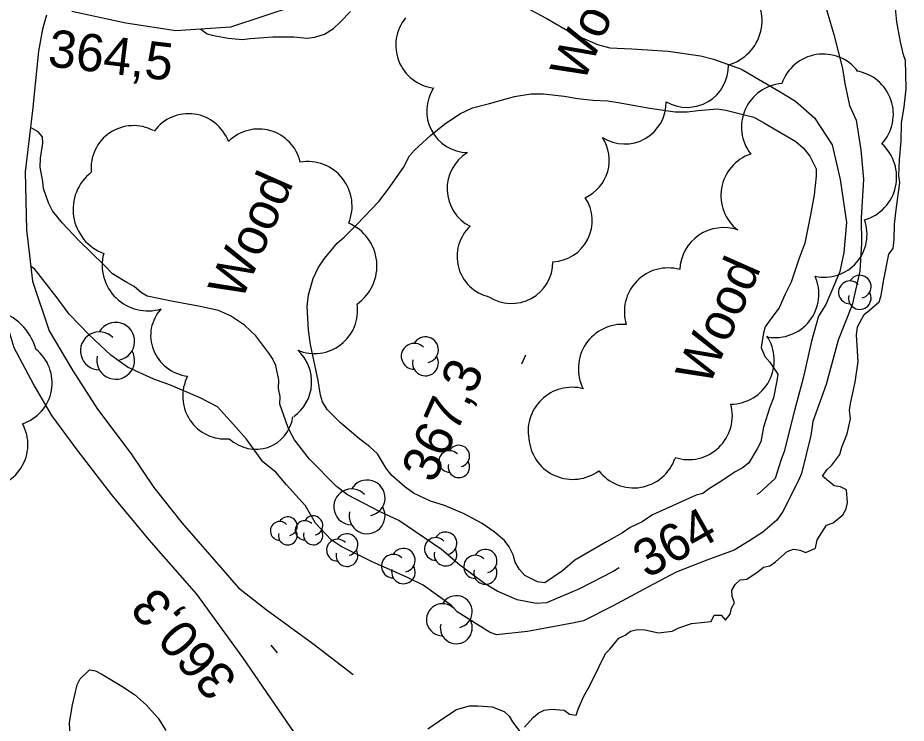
# Model space of a CAD drawing. Extents: x 287698 to 290158, y 5234163 to 5237182.
# Drawn here: x 289209.7 to 289281.1, y 5235213.3 to 5235270 of the extents above; entities that cross this region are included whole.
import ezdxf

# ---------------------------------------------------------------- set-up
doc = ezdxf.new("R2010")
doc.units = 0
for name, color, linetype in [('Niveau 19', 7, 'Continuous'), ('Niveau 2', 7, 'Continuous'), ('Niveau 3', 7, 'Continuous'), ('Niveau 4', 7, 'Continuous'), ('Niveau 44', 7, 'Continuous')]:
    doc.layers.add(name, color=color, linetype=linetype)

msp = doc.modelspace()

# ---------------------------------------------------------------- linework, layer by layer
at = {"layer": 'Niveau 19'}
for points in [[(289232.57, 5235211.58), (289227.76, 5235218.58), (289224.07, 5235223.68), (289220.24, 5235228.03), (289217.23, 5235231.65), (289214.46, 5235235.29), (289212.4, 5235238.04), (289210.9, 5235240.6), (289209.38, 5235243.49), (289208.5, 5235246.43), (289207.63, 5235250.16), (289207.48, 5235253.53), (289207.66, 5235257.1), (289208.2, 5235260.15), (289208.45, 5235264.13), (289208.52, 5235267.65), (289208.02, 5235270.78), (289206.62, 5235272.53), (289205, 5235274.04), (289203.18, 5235274.74), (289201.27, 5235274.81)], [(289231.96, 5235270.99), (289226.78, 5235269.26), (289222.39, 5235268.98), (289218.37, 5235269.59), (289214.03, 5235270.54)], [(289211.99, 5235270.23), (289211.65, 5235269.11), (289211.33, 5235267.33), (289210.86, 5235262.57), (289210.26, 5235257.65), (289210.39, 5235252.98), (289210.85, 5235248.84), (289212.2, 5235244.86), (289214.08, 5235241.69), (289216.09, 5235238.55), (289218.78, 5235234.95), (289220.62, 5235232.25), (289222.88, 5235229.39), (289225.43, 5235226.47), (289227.42, 5235224.17), (289229.63, 5235222.43), (289233.4, 5235219.7), (289236.64, 5235217.22)]]:
    msp.add_lwpolyline(points, dxfattribs=at)
at = {"layer": 'Niveau 2'}
for points in [[(289249.52, 5235271.4), (289252.15, 5235270.01), (289254.36, 5235268.71), (289256.28, 5235267.88), (289257.25, 5235267.62), (289259.02, 5235267.53), (289261.95, 5235267.35), (289264.54, 5235266.97), (289265.58, 5235266.71), (289267.83, 5235265.89), (289268.88, 5235265.27), (289270.96, 5235264.06), (289272.17, 5235263.31), (289273.72, 5235261.99), (289275.13, 5235259.81), (289275.78, 5235257.02), (289276.27, 5235253.55), (289276.06, 5235251.16), (289275.75, 5235249.63), (289275.1, 5235248.08), (289274.61, 5235246.97), (289274.03, 5235246.03), (289273.47, 5235244.03), (289272.79, 5235241.03), (289272.09, 5235238.45), (289271.27, 5235235.15), (289271.01, 5235234.43), (289270.54, 5235232.97), (289269.27, 5235231.79), (289269.08, 5235231.68)], [(289224.39, 5235269.11), (289224.91, 5235268.73), (289225.43, 5235268.59), (289226.58, 5235268.39), (289227.71, 5235268.27), (289228.34, 5235268.35), (289230.17, 5235268.49), (289231.87, 5235268.49), (289232.93, 5235268.39), (289233.56, 5235268.48), (289234.33, 5235268.71), (289235.04, 5235269.17), (289235.62, 5235269.7), (289236.41, 5235270.52)], [(289274.58, 5235270.97), (289275.27, 5235268.68), (289275.95, 5235265.94), (289276.14, 5235264.73), (289276.52, 5235262.97), (289277.05, 5235261.79), (289277.43, 5235259.42), (289277.65, 5235257.05), (289277.45, 5235253.91), (289277.49, 5235251.87), (289277.36, 5235249.66), (289276.73, 5235246.93), (289275.6, 5235244.11), (289274.65, 5235240.52), (289273.58, 5235237.57), (289273.41, 5235236.43), (289272.67, 5235233.37), (289272.41, 5235232.8), (289271.17, 5235230.33), (289270.67, 5235229.62), (289269.55, 5235228.66), (289268.43, 5235227.92), (289267.25, 5235227.22), (289265.06, 5235226.41), (289262.58, 5235225.43), (289260.32, 5235224.24), (289257.54, 5235222.74), (289255.13, 5235221.52), (289254.26, 5235221.33), (289250.63, 5235220.67), (289248.16, 5235220.41), (289247.59, 5235220.62), (289245, 5235222.25), (289244.53, 5235222.76), (289242.25, 5235224.4), (289241.04, 5235224.97), (289238.11, 5235226.29), (289235.67, 5235227.49), (289234.85, 5235228.04), (289233.61, 5235229.38), (289232.81, 5235230.78), (289231.28, 5235232.47)], [(289260.7, 5235230.05), (289259.87, 5235229.48), (289258.89, 5235229.02), (289258.29, 5235228.6), (289256.99, 5235227.88), (289254.45, 5235226.41), (289253.45, 5235225.54), (289252.04, 5235224.57), (289251.44, 5235224.65), (289250.44, 5235225.17), (289249.99, 5235225.64), (289249.65, 5235226.25), (289249.49, 5235226.84), (289249.18, 5235227.47), (289248.8, 5235227.98), (289247.97, 5235228.68), (289246.99, 5235229.36), (289245.55, 5235230.14), (289243.96, 5235230.8), (289242.84, 5235231.16), (289241.49, 5235231.79), (289240.79, 5235232.3), (289239.75, 5235233.21), (289239.3, 5235233.76), (289238.58, 5235234.96), (289237.98, 5235235.51), (289237.02, 5235236.25), (289235.6, 5235237.46), (289234.55, 5235238.51), (289234.17, 5235239.13), (289234, 5235239.67), (289233.81, 5235240.86), (289233.2, 5235243.75), (289233.04, 5235244.89), (289232.93, 5235246.8), (289233.05, 5235247.74), (289233.41, 5235249.05), (289233.82, 5235249.91), (289234.34, 5235250.68), (289235.35, 5235251.9), (289235.9, 5235252.39), (289236.94, 5235253.43), (289238.7, 5235255.25), (289239.47, 5235256.27), (289240.67, 5235257.99), (289241.16, 5235258.92), (289241.56, 5235259.37), (289242.85, 5235260.57), (289243.98, 5235261.47), (289245.21, 5235262.31), (289246.22, 5235262.78), (289247.58, 5235263.13), (289249.59, 5235263.69), (289250.91, 5235263.9), (289251.93, 5235263.9), (289253.6, 5235263.73), (289254.68, 5235263.54), (289255.9, 5235263.41), (289257.09, 5235263.36), (289257.94, 5235263.21), (289260.48, 5235262.76), (289262.52, 5235262.46), (289263.47, 5235262.46), (289264.37, 5235262.58), (289265.89, 5235262.7), (289266.58, 5235262.6), (289268.82, 5235262.04), (289269.69, 5235261.54), (289272.21, 5235260.08), (289272.82, 5235259.53), (289273.32, 5235258.91), (289273.83, 5235257.87), (289273.83, 5235257.28), (289273.67, 5235255.78), (289273.38, 5235254.19), (289272.92, 5235251.91), (289272.45, 5235250.62), (289271.84, 5235248.76), (289271.34, 5235247.79), (289270.88, 5235246.69), (289270.12, 5235245.71), (289269.75, 5235245.18), (289269.62, 5235244.68), (289269.43, 5235243.51), (289269.71, 5235242.79), (289270.12, 5235242.34), (289270.76, 5235241.37), (289270.68, 5235240.82), (289270.42, 5235239.46), (289270.13, 5235238.72), (289269.6, 5235237.11), (289269.39, 5235235.92), (289269.09, 5235235.35), (289268.42, 5235234.23), (289267.97, 5235233.86), (289267.34, 5235233.52), (289266.26, 5235232.78), (289265.19, 5235232.12), (289264.72, 5235231.77), (289264.19, 5235231.62), (289260.7, 5235230.05)], [(289231.39, 5235237.13), (289230.75, 5235238.96), (289230.77, 5235239.57), (289230.63, 5235240.22), (289230.66, 5235240.89), (289230.42, 5235242.05), (289230.16, 5235242.62), (289229.85, 5235243.06), (289228.81, 5235244.44), (289227.89, 5235245.31), (289226.76, 5235246.06), (289225.8, 5235246.49), (289224.34, 5235246.81), (289222.17, 5235247.2), (289220.07, 5235247.63), (289219.63, 5235247.91), (289219.03, 5235248.42), (289218.44, 5235248.73), (289217.3, 5235249.43), (289216.61, 5235250.13), (289214.59, 5235252.11), (289213.27, 5235253.5), (289212.47, 5235254.49), (289212.14, 5235255.14), (289211.73, 5235256.29), (289211.69, 5235256.86), (289211.47, 5235258.02), (289211.49, 5235258.75), (289211.7, 5235259.93), (289211.67, 5235260.44), (289211.31, 5235260.85), (289210.69, 5235261.2)], [(289231.28, 5235232.47), (289230.41, 5235233.47), (289229.37, 5235234.3), (289228.06, 5235236.14), (289227.02, 5235237.32), (289225.72, 5235238.73), (289224.34, 5235239.47), (289221.95, 5235240.49), (289220.61, 5235240.97), (289218.49, 5235241.94), (289217.16, 5235242.89), (289215.4, 5235244.54), (289213.81, 5235246.2), (289212.83, 5235247.5), (289211.01, 5235249.84), (289210.72, 5235250.03)], [(289258.01, 5235225.8), (289257.52, 5235225.5), (289254.83, 5235224.1), (289252.17, 5235222.98), (289251.34, 5235222.91), (289249.82, 5235223.21), (289248.21, 5235223.92), (289247.19, 5235224.53), (289245.19, 5235225.99), (289243.72, 5235227.26), (289240.29, 5235229.6), (289238.8, 5235230.28), (289236.17, 5235231.66), (289235.3, 5235232.34), (289233.13, 5235234.54), (289231.91, 5235236.07), (289231.53, 5235236.77), (289231.39, 5235237.13)]]:
    msp.add_lwpolyline(points, dxfattribs=at)
at = {"layer": 'Niveau 3'}
for p, q in [((289250.18, 5235242.19), (289250.5, 5235242.92)), ((289230.56, 5235218.96), (289230.04, 5235219.57))]:
    msp.add_line(p, q, dxfattribs=at)
at = {"layer": 'Niveau 4'}
for points in [[(289280.11, 5235252.16), (289280.13, 5235253.44), (289280.26, 5235254.59), (289280.56, 5235256.79), (289280.49, 5235257.31), (289280.54, 5235258.61), (289280.66, 5235260.11), (289280.71, 5235261.56), (289280.92, 5235262.86), (289281.08, 5235264.32), (289281.04, 5235265.48), (289281.03, 5235266.58), (289280.87, 5235267.06), (289280.63, 5235268.09), (289280.32, 5235269.71), (289280.23, 5235270.78)], [(289250.41, 5235212.96), (289251.1, 5235213.74), (289251.51, 5235214.11), (289251.99, 5235214.33), (289252.56, 5235214.41), (289253.58, 5235214.35), (289254.03, 5235214.01), (289254.55, 5235213.94), (289254.71, 5235214.42), (289255.15, 5235215.42), (289255.66, 5235216.32), (289256.39, 5235217.84), (289256.9, 5235218.89), (289257.27, 5235219.25), (289257.99, 5235220.14), (289258.48, 5235220.37), (289258.92, 5235220.68), (289259.46, 5235220.83), (289260.08, 5235220.8), (289261.17, 5235220.55), (289262.26, 5235220.7), (289262.81, 5235220.95), (289263.81, 5235221.3), (289264.86, 5235221.42), (289265.4, 5235221.47), (289265.65, 5235221.97), (289266.2, 5235221.98), (289266.56, 5235221.59), (289266.94, 5235222.05), (289267.05, 5235222.54), (289267.29, 5235222.98), (289267.09, 5235223.49), (289267.06, 5235224), (289267.34, 5235224.44), (289267.73, 5235224.82), (289268.27, 5235224.88), (289269.19, 5235225.49), (289269.62, 5235225.84), (289270.11, 5235225.94), (289270.57, 5235226.27), (289271.51, 5235227.09), (289272.01, 5235227.29), (289272.52, 5235227.2), (289273.02, 5235227.01), (289273.79, 5235227.38), (289273.93, 5235228.05), (289274.66, 5235229.22), (289275.21, 5235229.41), (289275.99, 5235230.06), (289276.26, 5235230.54), (289276.35, 5235231.05), (289276.28, 5235232.06), (289275.8, 5235232.31), (289275.3, 5235232.38), (289274.34, 5235233.15), (289274.7, 5235233.66), (289275.11, 5235234.05), (289275.75, 5235234.9), (289275.91, 5235235.5), (289276.34, 5235236.56), (289276.6, 5235237.77), (289276.52, 5235238.48), (289276.59, 5235239.01), (289276.98, 5235240.71), (289277.21, 5235242.38), (289277.08, 5235244.51), (289277.17, 5235245.17), (289277.71, 5235246.17), (289278.14, 5235246.5), (289278.91, 5235247.19), (289279.06, 5235247.7), (289279.26, 5235248.84), (289279.69, 5235251.02), (289280.03, 5235251.47), (289280.11, 5235252.16)], [(289213.96, 5235210.29), (289213.84, 5235213.36), (289214.08, 5235214.76), (289214.45, 5235216.38), (289214.69, 5235216.85), (289215.43, 5235217.59), (289215.93, 5235217.5), (289216.43, 5235217.23), (289218.03, 5235216.28), (289219.06, 5235215.59), (289219.99, 5235214.77), (289220.96, 5235213.69), (289221.58, 5235212.71)], [(289242.63, 5235212.83), (289244, 5235213.77), (289244.94, 5235214.4), (289245.99, 5235214.7), (289246.66, 5235214.7), (289247.8, 5235214.6), (289248.77, 5235214.23), (289249.17, 5235213.87), (289249.43, 5235213.4), (289250.03, 5235212.62)]]:
    msp.add_lwpolyline(points, dxfattribs=at)
at = {"layer": 'Niveau 44'}
for centre, radius, start, end in [((289265.799, 5235269.81), 3.695, 285.5604, 47.18561), ((289243.528, 5235267.827), 3.475, 140.66524, 262.76263), ((289263.462, 5235266.154), 3.33, 239.67009, 1.65005), ((289245.894, 5235262.536), 3.357, 146.66681, 268.55924), ((289258.453, 5235263.206), 3.328, 237.79671, 1.28085), ((289253.891, 5235258.577), 3.327, 294.74638, 33.02894), ((289276.715, 5235257.218), 3.595, 286.39801, 48.00964), ((289247.568, 5235256.281), 3.39, 121.23589, 243.02062), ((289252.516, 5235253.712), 3.326, 272.83475, 33.66784), ((289248.31, 5235250.83), 3.332, 133.16804, 256.46825), ((289249.351, 5235250.377), 3.329, 236.8458, 0.21911), ((289277.345, 5235248.401), 0.914, 282.26917, 149.72626), ((289276.559, 5235247.944), 0.914, 44.11537, 269.80396), ((289277.345, 5235247.487), 0.914, 166.93686, 29.62123), ((289217.545, 5235244.003), 1.524, 282.26917, 149.72626), ((289216.234, 5235243.24), 1.524, 44.11537, 269.80396), ((289242.438, 5235243.32), 1.044, 282.26917, 149.72626), ((289217.545, 5235242.478), 1.524, 166.93686, 29.62123), ((289241.54, 5235242.798), 1.044, 44.11537, 269.80396), ((289242.438, 5235242.276), 1.044, 166.93686, 29.62123), ((289245.126, 5235234.777), 0.867, 282.26917, 149.72626), ((289244.38, 5235234.343), 0.867, 44.11537, 269.80396), ((289245.126, 5235233.909), 0.867, 166.93686, 29.62123), ((289237.751, 5235231.409), 1.441, 282.26917, 149.72626), ((289236.512, 5235230.688), 1.441, 44.11537, 269.80396), ((289237.751, 5235229.968), 1.441, 166.93686, 29.62123), ((289231.379, 5235229.137), 0.754, 282.26917, 149.72626), ((289233.417, 5235229.187), 0.774, 282.26917, 149.72626), ((289230.731, 5235228.76), 0.754, 44.11537, 269.80396), ((289232.752, 5235228.801), 0.774, 44.11537, 269.80396), ((289231.379, 5235228.383), 0.754, 166.93686, 29.62123), ((289233.417, 5235228.414), 0.774, 166.93686, 29.62123), ((289236.13, 5235227.652), 0.877, 282.26917, 149.72626), ((289244.053, 5235227.759), 0.911, 282.26917, 149.72626), ((289235.375, 5235227.213), 0.877, 44.11537, 269.80396), ((289243.27, 5235227.304), 0.911, 44.11537, 269.80396), ((289236.13, 5235226.775), 0.877, 166.93686, 29.62123), ((289239.854, 5235225.925), 0.947, 44.11537, 269.80396), ((289240.668, 5235226.399), 0.947, 282.26917, 149.72626), ((289244.053, 5235226.849), 0.911, 166.93686, 29.62123), ((289247.253, 5235226.332), 0.934, 282.26917, 149.72626), ((289246.45, 5235225.865), 0.934, 44.11537, 269.80396), ((289240.668, 5235225.451), 0.947, 166.93686, 29.62123), ((289247.253, 5235225.398), 0.934, 166.93686, 29.62123), ((289244.918, 5235222.258), 1.288, 282.26917, 149.72626), ((289243.811, 5235221.614), 1.288, 44.11537, 269.80396), ((289244.918, 5235220.97), 1.288, 166.93686, 29.62123)]:
    msp.add_arc(centre, radius, start, end, dxfattribs=at)
for centre, major_axis, ratio, start_param, end_param in [((289274.405, 5235263.589), (-3.473, -0.565), 0.999941, 3.636133, 5.788645), ((289276.534, 5235262.271), (-1.154, 3.321), 0.999942, 3.633828, 5.790949), ((289271.36, 5235261.23), (-1.42, -3.222), 0.999941, 3.636476, 5.788302), ((289223.416, 5235258.889), (-1.956, 2.823), 0.99207, 4.465254, 6.61704), ((289218.983, 5235257.923), (-0.604, 3.378), 0.996398, 5.616192, 7.772057), ((289229.034, 5235257.647), (1.206, 3.217), 0.999385, 5.297747, 7.425495), ((289269.703, 5235255.735), (-0.59, -3.469), 0.999942, 3.635158, 5.78962), ((289232.962, 5235254.885), (3.254, 1.5), 0.999934, 5.457202, 7.585172), ((289217.896, 5235254.619), (-3.735, -0.584), 0.998166, 5.217088, 7.343676), ((289234.796, 5235250.069), (3.724, 0.379), 0.999995, 5.220783, 7.347746), ((289266.398, 5235249.63), (-2.584, -2.391), 0.999942, 3.635528, 5.492917), ((289274.486, 5235252.608), (2.596, -2.266), 0.999978, 5.217526, 7.344628), ((289220.142, 5235250.139), (-2.562, -2.65), 0.999516, 5.222561, 7.343043), ((289261.947, 5235246.389), (-2.473, -2.507), 0.999941, 3.651655, 5.787423), ((289270.55, 5235247.818), (2.158, 2.769), 0.999942, 3.633217, 5.791561), ((289206.926, 5235242.231), (1.04, 4.23), 0.999831, 5.218071, 7.34518), ((289233.522, 5235246.476), (2.129, -2.725), 0.999731, 5.221059, 7.342888), ((289223.779, 5235244.421), (3.39, -0.523), 0.951355, 2.56843, 4.723971), ((289258.29, 5235241.811), (-2.961, 1.977), 0.999995, 5.219654, 7.344668), ((289266.96, 5235242.468), (1.645, 3.109), 0.999942, 3.633959, 5.790819), ((289208.99, 5235240.663), (0.612, 3.396), 0.999985, 3.632197, 5.792581), ((289229.894, 5235240.765), (-1.211, 3.213), 0.989783, 3.391699, 5.182809), ((289226.318, 5235239.582), (0.567, -3.383), 0.986545, 4.06058, 6.219146), ((289254.218, 5235236.78), (-2.416, -2.57), 0.999941, 3.637641, 5.701768), ((289263.586, 5235238.014), (0.029, 3.521), 0.999794, 2.838067, 4.989642), ((289228.647, 5235238.722), (1.227, -3.211), 0.919282, 5.222365, 7.284044), ((289207.027, 5235235.692), (3.219, -1.275), 0.999932, 5.015036, 7.169533), ((289254.276, 5235236.421), (3.189, -1.49), 0.999985, 3.710415, 5.790378), ((289259.174, 5235235.729), (3.467, 0.564), 0.999942, 3.63159, 5.793188)]:
    msp.add_ellipse(centre, major_axis=major_axis, ratio=ratio, start_param=start_param, end_param=end_param, dxfattribs=at)

# ---------------------------------------------------------------- texts
at = {"layer": 'Niveau 2'}
msp.add_text('364', height=2.9999, rotation=29.4013, dxfattribs=at).set_placement((289260.24, 5235224.89))
at = {"layer": 'Niveau 3'}
for s, height, rotation, p in [('364,5', 2.9999, 353.19433, (289212.01, 5235266.14)), ('367,3', 3, 66.1217, (289243.14, 5235232.5)), ('360,3', 3, 131.30828, (289227.44, 5235216.86))]:
    msp.add_text(s, height=height, rotation=rotation, dxfattribs=at).set_placement(p)
at = {"layer": 'Niveau 44'}
for p in [(289255.11, 5235264.7), (289227.63, 5235247.16), (289265.2, 5235240.3)]:
    msp.add_text('Wood', height=3, rotation=66.1217, dxfattribs=at).set_placement(p)

doc.saveas('drawing.dxf')
